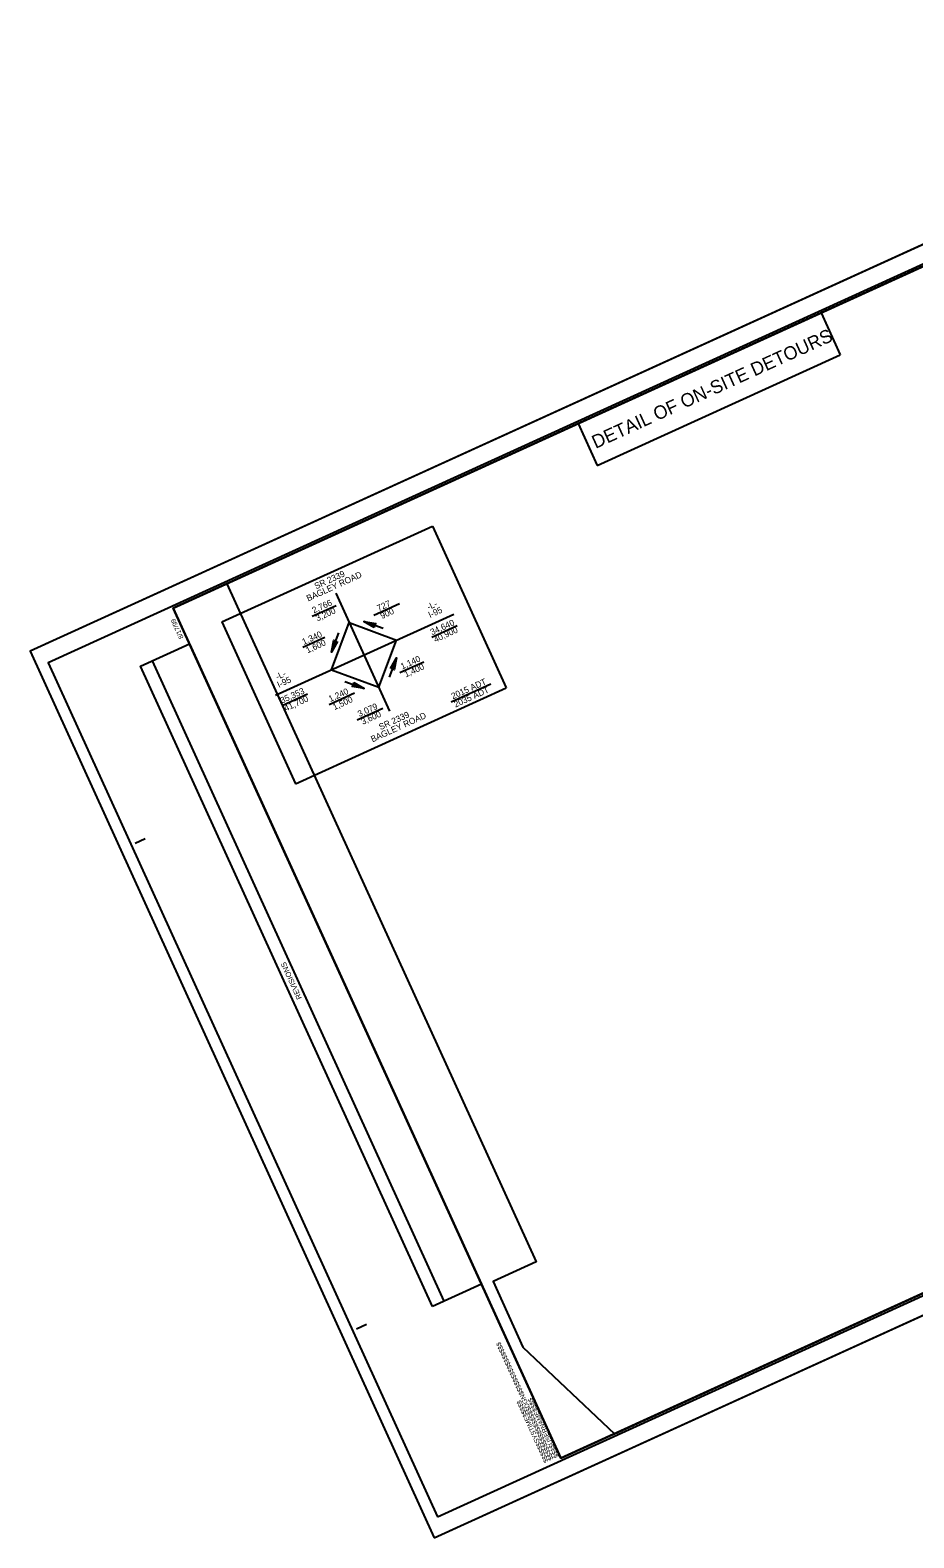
# Model space of a CAD drawing. Extents: x 2246788 to 2248774, y 662010 to 663780.
# Drawn here: x 2246788 to 2247781, y 662010 to 663705 of the extents above; entities that cross this region are included whole.
import ezdxf

# ---------------------------------------------------------------- set-up
doc = ezdxf.new("R2010")
doc.units = 0
for name, color, linetype in [('Prop Dimension', 7, 'Continuous'), ('Prop Dimension Text', 7, 'Continuous'), ('Prop Terminator CELL', 7, 'Continuous'), ('Sheet Block Revision CELL', 7, 'Continuous'), ('Sheet Clip Boundary CELL', 7, 'Continuous'), ('Sheet Cutting Line CELL', 7, 'Continuous'), ('Sheet Plan CELL', 7, 'Continuous'), ('Sheet Plan Layout CELL', 7, 'Continuous'), ('Sheet Plot Border Inside CELL', 7, 'Continuous'), ('Sheet Plot Border Outside CELL', 7, 'Continuous')]:
    doc.layers.add(name, color=color, linetype=linetype)

msp = doc.modelspace()

# ---------------------------------------------------------------- linework, layer by layer
at = {"layer": 'Prop Dimension Text'}
for p, q in [((2247003.2, 663039.7), (2247239.8, 663147.5)), ((2247239.8, 663147.5), (2247322.8, 662965.5)), ((2247131.4, 663072), (2247191.7, 662939.5)), ((2247174.2, 663047.4), (2247202.8, 663060.4)), ((2247063.6, 662957.3), (2247264.1, 663048.6)), ((2247104.8, 663046), (2247131.7, 663058.2)), ((2247003.2, 663039.7), (2247086.2, 662857.7)), ((2247126.5, 663005.8), (2247134.7, 663027.5)), ((2247126.6, 662986), (2247146.4, 663039)), ((2247146.4, 663039), (2247199.4, 663019.2)), ((2247184.5, 663032.2), (2247162.8, 663040.3)), ((2247239.1, 663022.5), (2247267.7, 663035.5)), ((2247119.1, 663022.3), (2247094.2, 663010.9)), ((2247179.6, 662966.2), (2247199.4, 663019.2)), ((2247199.5, 662999.3), (2247191.3, 662977.6)), ((2247203.3, 662982.7), (2247230.2, 662995)), ((2247126.6, 662986), (2247179.6, 662966.2)), ((2247126.6, 662986), (2247179.6, 662966.2)), ((2247071, 662945.9), (2247099.6, 662958.9)), ((2247086.2, 662857.7), (2247322.8, 662965.5)), ((2247152.5, 662959.7), (2247123.9, 662946.6)), ((2247141.5, 662972.9), (2247163.2, 662964.8)), ((2247260.9, 662949.9), (2247305.5, 662970.3)), ((2247155.5, 662929.6), (2247184.1, 662942.7))]:
    msp.add_line(p, q, dxfattribs=at)
at = {"layer": 'Prop Terminator CELL'}
for points in [[(2247174.6, 663033.4), (2247162.8, 663040.3), (2247176.3, 663037.8), (2247173.9, 663036.2)], [(2247133.4, 663017.6), (2247126.5, 663005.8), (2247129, 663019.3), (2247130.7, 663016.9)], [(2247192.6, 662987.5), (2247199.5, 662999.3), (2247197, 662985.8), (2247195.3, 662988.2)], [(2247151.4, 662971.7), (2247163.2, 662964.8), (2247149.7, 662967.3), (2247152.1, 662969)]]:
    msp.add_lwpolyline(points, close=True, dxfattribs=at)
at = {"layer": 'Sheet Block Revision CELL'}
msp.add_line((2247253.1, 662276.4), (2246925.2, 662995.8), dxfattribs=at)
msp.add_lwpolyline([(2247239.9, 662270.3), (2246912, 662989.8), (2246967.1, 663014.9), (2247294.9, 662295.5)], close=True, dxfattribs=at)
at = {"layer": 'Sheet Clip Boundary CELL'}
msp.add_lwpolyline([(2248573, 662641.6), (2248489.8, 662824.8), (2248241.7, 663371.1), (2248234.7, 663383.7), (2248212.2, 663373.7), (2248115.5, 663587), (2247008.7, 663082.6), (2247356.3, 662320.4), (2247308, 662298.4), (2247341.5, 662224.7), (2247444.4, 662127.3)], close=True, dxfattribs=at)
at = {"layer": 'Sheet Cutting Line CELL'}
for p, q in [((2248319.8, 663704.8), (2246787.9, 663006.7)), ((2246787.9, 663006.7), (2247241.9, 662010.3)), ((2247241.9, 662010.3), (2248773.9, 662708.4))]:
    msp.add_line(p, q, dxfattribs=at)
at = {"layer": 'Sheet Plan CELL'}
for p, q in [((2247676.6, 663387), (2247698.2, 663339.8)), ((2247425.2, 663215.4), (2247698.2, 663339.8)), ((2247403.7, 663262.6), (2247425.2, 663215.4)), ((2246948.7, 663055.3), (2246948.7, 663055.3)), ((2246905.8, 662791.2), (2246917.2, 662796.4)), ((2247154.6, 662245.2), (2247166, 662250.4)), ((2247384.1, 662099.8), (2247384.1, 662099.8))]:
    msp.add_line(p, q, dxfattribs=at)
for points in [[(2248313.7, 663677.3), (2246948.7, 663055.3), (2247384.1, 662099.8), (2248749.1, 662721.8)], [(2247384.1, 662099.8), (2246948.7, 663055.2), (2248131.6, 663594.3), (2248193.9, 663457.8), (2248375.9, 663540.7), (2248749.1, 662721.8)]]:
    msp.add_lwpolyline(points, close=True, dxfattribs=at)
at = {"layer": 'Sheet Plan Layout CELL'}
msp.add_lwpolyline([(2246948.7, 663055.2), (2247384.1, 662099.8), (2248749, 662721.8), (2248401.3, 663484.8), (2248183.6, 663385.6), (2248095.9, 663578.1)], close=True, dxfattribs=at)
at = {"layer": 'Sheet Plot Border Inside CELL'}
msp.add_lwpolyline([(2247245.5, 662033.9), (2248761.5, 662724.7), (2248324, 663684.7), (2246808, 662993.9)], close=True, dxfattribs=at)
at = {"layer": 'Sheet Plot Border Outside CELL'}
msp.add_lwpolyline([(2247241.9, 662010.3), (2248773.9, 662708.4), (2248319.8, 663704.8), (2246787.9, 663006.7)], close=True, dxfattribs=at)

# ---------------------------------------------------------------- texts
at = {"layer": 'Prop Dimension'}
msp.add_text('DETAIL OF ON-SITE DETOURS', height=15, rotation=24.4979, dxfattribs=at).set_placement((2247423.3, 663234.1))
at = {"layer": 'Prop Dimension Text'}
for s, p in [('BAGLEY ROAD', (2247100.3, 663062.6)), ('SR 2339', (2247109.2, 663076.3)), ('2,766', (2247106.5, 663049.2)), ('727', (2247179.5, 663051.5)), ('-L-', (2247235.7, 663052.9)), ('3,200', (2247110.6, 663040.2)), ('900', (2247183.3, 663042.9)), ('I-95', (2247237.2, 663044)), ('1,340', (2247095.3, 663013.7)), ('34,640', (2247239.4, 663024.6)), ('40,900', (2247243.2, 663016.4)), ('1,600', (2247099.6, 663004.3)), ('1,140', (2247206, 662986.1)), ('1,400', (2247210.1, 662977.3)), ('-L-', (2247065.7, 662974.5)), ('I-95', (2247067.3, 662965.6)), ('2015 ADT', (2247262.9, 662952.6)), ('35,353', (2247070.8, 662947.8)), ('1,240', (2247125.1, 662949.6)), ('2035 ADT', (2247265.9, 662943.4)), ('41,700', (2247075.2, 662939)), ('1,500', (2247129.8, 662940.5)), ('3,079', (2247157.8, 662932.7)), ('3,600', (2247161.7, 662924)), ('BAGLEY ROAD', (2247172.6, 662904.3)), ('SR 2339', (2247181.6, 662918))]:
    msp.add_text(s, height=7, rotation=24.4979, dxfattribs=at).set_placement(p)
at = {"layer": 'Sheet Block Revision CELL'}
msp.add_text('REVISIONS', height=6, rotation=114.4979, dxfattribs=at).set_placement((2247093.4, 662617))
at = {"layer": 'Sheet Plan CELL'}
for s, p in [('8/17/99', (2246960.4, 663021.9)), ('$$$$$$$$$$$$$$$$DGN$$$$$$$$$$$$$$$$', (2247376.2, 662098.8)), ('$$$$$$SYSTIME$$$$$', (2247370.6, 662096.2)), ('$$$$USERNAME$$$$', (2247382.1, 662101.5))]:
    msp.add_text(s, height=5.25, rotation=114.4979, dxfattribs=at).set_placement(p)

doc.saveas('drawing.dxf')
